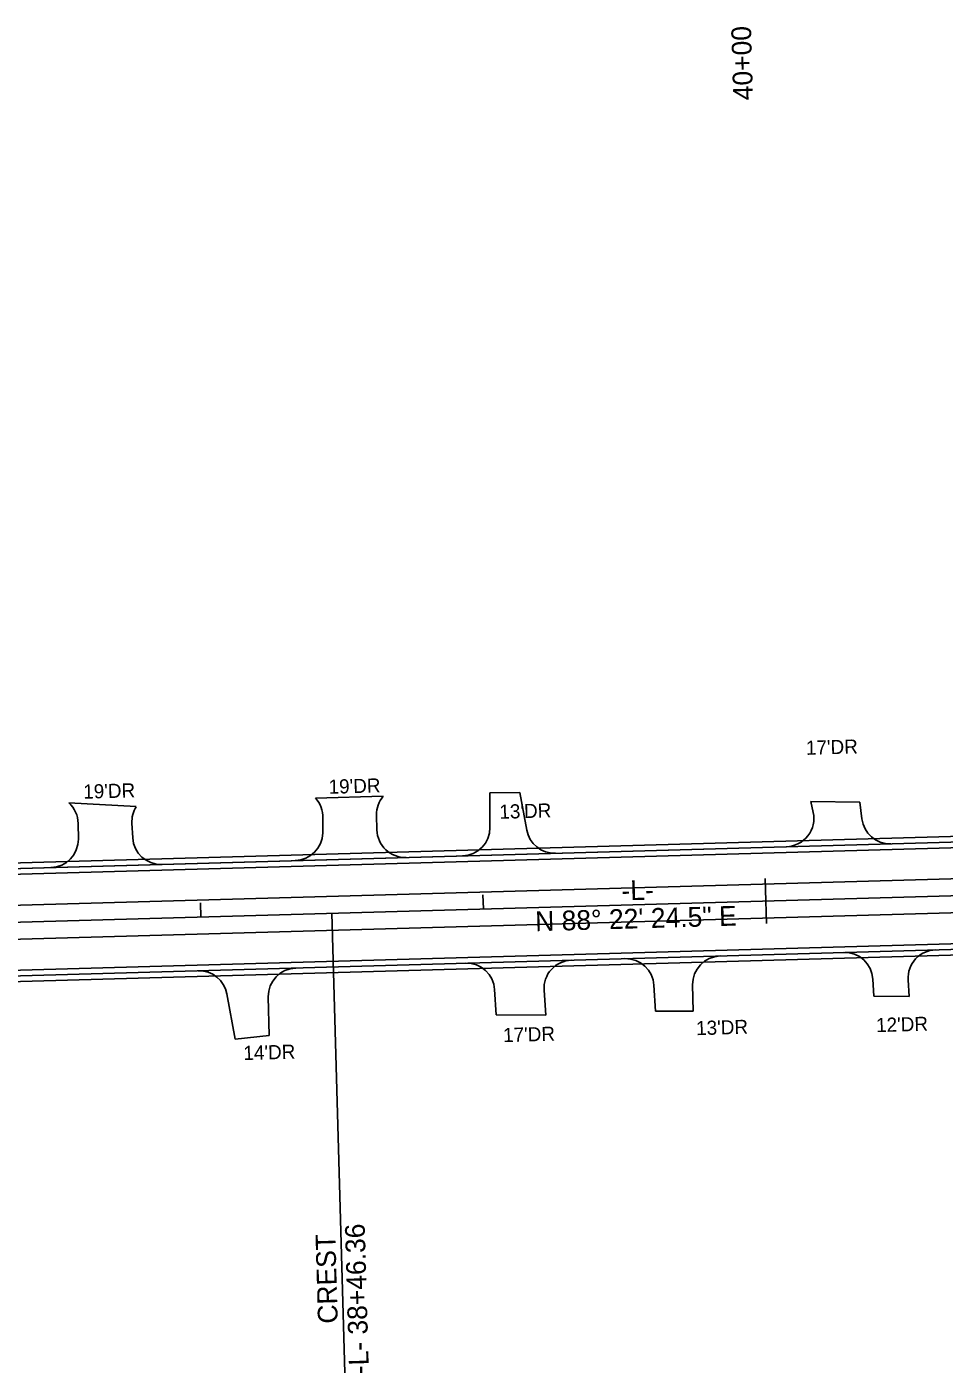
# Model space of a CAD drawing. Extents: x 1755545 to 1761252, y 736169 to 737766.
# Drawn here: x 1758421.9 to 1758746.3, y 736843.8 to 737320.3 of the extents above; entities that cross this region are included whole.
import ezdxf

# ---------------------------------------------------------------- set-up
doc = ezdxf.new("R2010")
doc.units = 0
for name, color, linetype in [('Exist Contamination Potential Cell', 7, 'Continuous'), ('Old_Level_1', 7, 'Continuous'), ('Old_Level_15', 7, 'Continuous'), ('Prop Horizontal Alignment', 7, 'Continuous'), ('Prop Horizontal Alignment Direction Label', 7, 'Continuous'), ('Prop Horizontal Alignment Tick Label', 7, 'Continuous'), ('Prop Horizontal Alignment Tick Large', 7, 'Continuous'), ('Prop Horizontal Alignment Tick Small', 7, 'Continuous'), ('Prop Lane Lines', 7, 'Continuous'), ('Prop Paved Shoulder', 7, 'Continuous'), ('Prop Shade Light', 7, 'Continuous'), ('Scratch_Level_4', 7, 'Continuous'), ('Scratch_Level_6', 7, 'Continuous')]:
    doc.layers.add(name, color=color, linetype=linetype)

msp = doc.modelspace()

# ---------------------------------------------------------------- linework, layer by layer
at = {"layer": 'Exist Contamination Potential Cell'}
for p, q in [((1757498.66, 736960.29), (1760222.11, 737037.63)), ((1757497.77, 736994.28), (1758821.01, 737031.85))]:
    msp.add_line(p, q, dxfattribs=at)
at = {"layer": 'Old_Level_1'}
for p, q in [((1758436.68, 737045.71), (1758460.53, 737044.32)), ((1758523.93, 737047.31), (1758547.96, 737048.05)), ((1758585.65, 737049.17), (1758596.31, 737049.35)), ((1758585.71, 737036.94), (1758585.65, 737049.17)), ((1758598.71, 737036.05), (1758596.31, 737049.35)), ((1758699.22, 737046.19), (1758700.08, 737042.31)), ((1758699.22, 737046.19), (1758716.58, 737045.96)), ((1758716.58, 737045.96), (1758717.28, 737040.03)), ((1758526.63, 737040.27), (1758526.52, 737035.01)), ((1758545.58, 737041.31), (1758545.73, 737036.06)), ((1758440.02, 737038.36), (1758440.08, 737032.87)), ((1758459.04, 737038.45), (1758459.34, 737033.29)), ((1758721.14, 736983.29), (1758721.49, 736977.18)), ((1758733.99, 736977.07), (1758733.65, 736983.07)), ((1758495.62, 736961.99), (1758492.64, 736978.06)), ((1758587.95, 736970.62), (1758587.35, 736979.59)), ((1758605.45, 736970.51), (1758604.86, 736979.31)), ((1758643.71, 736981.1), (1758644.24, 736971.9)), ((1758657.61, 736971.94), (1758657.38, 736981.23)), ((1758507.56, 736963.33), (1758507.27, 736977)), ((1758733.99, 736977.07), (1758721.49, 736977.18)), ((1758587.95, 736970.62), (1758605.45, 736970.51)), ((1758657.61, 736971.94), (1758644.24, 736971.9)), ((1758495.62, 736961.99), (1758507.56, 736963.33))]:
    msp.add_line(p, q, dxfattribs=at)
for centre, start, end in [((1758430.02, 737038.25), 0.6283, 48.2449), ((1758516.63, 737040.47), 358.8534, 43.136), ((1758555.58, 737041.58), 139.6475, 181.5475), ((1758469.02, 737039.03), 148.1012, 183.3216), ((1758690.31, 737040.15), 271.6265, 12.4644), ((1758727.21, 737041.2), 186.7062, 271.6265), ((1758555.72, 737036.33), 181.5475, 271.6265), ((1758575.71, 737036.89), 271.6265, 0.2563), ((1758608.55, 737037.83), 190.2404, 271.6265), ((1758430.08, 737032.76), 271.6265, 0.6283), ((1758469.32, 737033.87), 183.3215, 271.6265), ((1758516.53, 737035.21), 271.6265, 358.8534), ((1758711.15, 736982.72), 3.3128, 91.6265), ((1758743.63, 736983.64), 91.6265, 183.2375), ((1758577.38, 736978.92), 3.8323, 91.6265), ((1758614.83, 736979.98), 91.6265, 183.8323), ((1758633.73, 736980.52), 3.3231, 91.6265), ((1758667.38, 736981.47), 91.6265, 181.3938), ((1758482.81, 736976.23), 10.5132, 91.6265), ((1758517.27, 736977.21), 91.6265, 181.1913)]:
    msp.add_arc(centre, 10, start, end, dxfattribs=at)
at = {"layer": 'Old_Level_15'}
msp.add_line((1758529.75, 737006.58), (1758534.37, 736843.84), dxfattribs=at)
at = {"layer": 'Prop Horizontal Alignment'}
msp.add_line((1757285.64, 736971.25), (1760282.69, 737056.35), dxfattribs=at)
at = {"layer": 'Prop Horizontal Alignment Tick Large'}
for q in [(1758683.11, 737018.94), (1758683.56, 737002.94)]:
    msp.add_line((1758683.33, 737010.94), q, dxfattribs=at)
at = {"layer": 'Prop Horizontal Alignment Tick Small'}
for p, q in [((1758583.37, 737008.1), (1758583.23, 737013.1)), ((1758483.41, 737005.26), (1758483.27, 737010.26))]:
    msp.add_line(p, q, dxfattribs=at)
at = {"layer": 'Prop Lane Lines'}
for p, q in [((1757285.47, 736977.25), (1760207.53, 737060.22)), ((1757285.81, 736965.25), (1760207.87, 737048.23))]:
    msp.add_line(p, q, dxfattribs=at)
at = {"layer": 'Prop Paved Shoulder'}
for p, q in [((1757497.71, 736996.28), (1758820.95, 737033.85)), ((1757498.72, 736958.29), (1758854.08, 736996.78))]:
    msp.add_line(p, q, dxfattribs=at)
at = {"layer": 'Prop Shade Light'}
for p, q in [((1760222.11, 737037.63), (1757498.66, 736960.29)), ((1758820.95, 737033.85), (1757497.71, 736996.28)), ((1757497.77, 736994.28), (1758821.01, 737031.85)), ((1757498.72, 736958.29), (1758862.05, 736997.01))]:
    msp.add_line(p, q, dxfattribs=at)
at = {"layer": 'Scratch_Level_6'}
for p, q in [((1757497.65, 736998.28), (1758820.89, 737035.85)), ((1757498.78, 736956.29), (1758854.11, 736994.78))]:
    msp.add_line(p, q, dxfattribs=at)

# ---------------------------------------------------------------- texts
at = {"layer": 'Old_Level_15'}
for s, p in [('CREST', (1758531.88, 736861.41)), ('-L- 38+46.36', (1758542.89, 736843.48))]:
    msp.add_text(s, height=7, rotation=91.6265, dxfattribs=at).set_placement(p)
at = {"layer": 'Prop Horizontal Alignment Direction Label'}
for s, p in [('-L-', (1758632.31, 737011.11)), ('N 88%%d 22\' 24.5" E', (1758601.8, 737000.21))]:
    msp.add_text(s, height=7, rotation=1.6265, dxfattribs=at).set_placement(p)
at = {"layer": 'Prop Horizontal Alignment Tick Label'}
msp.add_text('40+00', height=7, rotation=91.6265, dxfattribs=at).set_placement((1758678.78, 737294.48))
at = {"layer": 'Scratch_Level_4'}
for s, p in [("17'DR", (1758697.54, 737062.64)), ("19'DR", (1758528.68, 737048.86)), ("19'DR", (1758441.88, 737047.12)), ("13'DR", (1758589.1, 737040.01)), ("13'DR", (1758658.7, 736963.41)), ("12'DR", (1758722.37, 736964.49)), ("17'DR", (1758590.41, 736960.96)), ("14'DR", (1758498.55, 736954.61))]:
    msp.add_text(s, height=5, rotation=1.6265, dxfattribs=at).set_placement(p)

doc.saveas('drawing.dxf')
